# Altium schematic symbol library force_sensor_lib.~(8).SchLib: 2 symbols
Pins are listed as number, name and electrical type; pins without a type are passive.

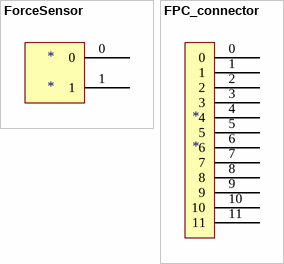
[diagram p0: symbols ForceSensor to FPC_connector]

## ForceSensor
designator *
footprint sensor_connector
pins: 0, 1

## FPC_connector
designator *
pins: 0, 1, 2, 3, 4, 5, 6, 7, 8, 9, 10, 11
